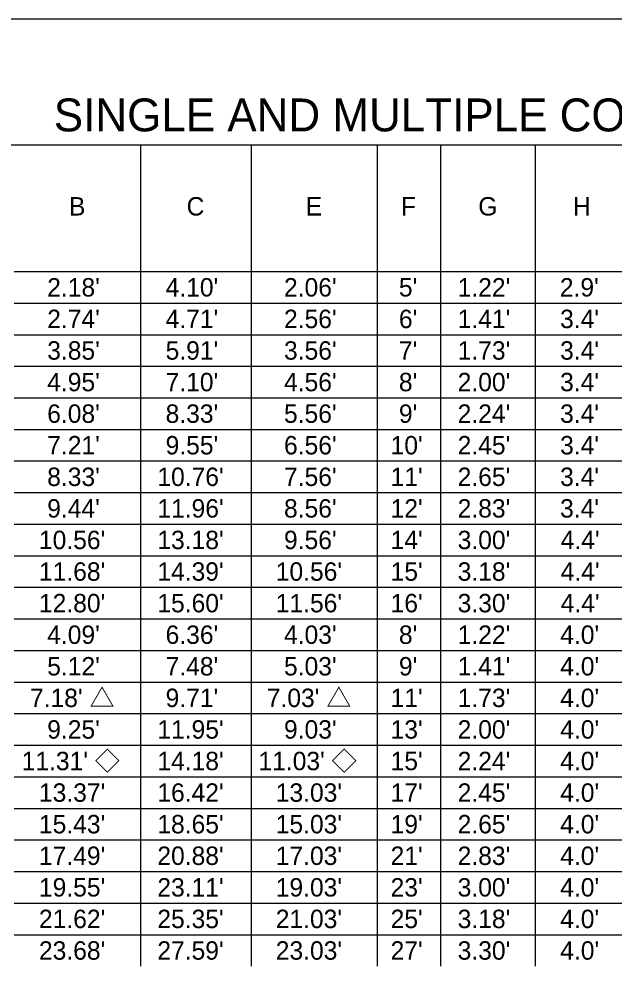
# Model space of a CAD drawing. Extents: x -1.3 to 14.6, y 0 to 8.4.
# Drawn here: x 4.058 to 6.32, y 4.842 to 8.43 of the extents above; entities that cross this region are included whole.
import ezdxf

# ---------------------------------------------------------------- set-up
doc = ezdxf.new("R2010")
doc.units = 0
doc.layers.add('Table', color=7, linetype='Continuous')

msp = doc.modelspace()

# ---------------------------------------------------------------- linework, layer by layer
at = {"layer": 'Table'}
msp.add_line((1.94, 8.43), (13.46, 8.43), dxfattribs=at)
for points in [[(13.46, 7.95), (11.78, 7.95), (10.1, 7.95), (8.42, 7.95), (8.06, 7.95), (6.38, 7.95), (6.02, 7.95), (5.66, 7.95), (5.42, 7.95), (4.94, 7.95), (4.52, 7.95), (4.04, 7.95), (3.62, 7.95), (3.2, 7.95), (2.9, 7.95), (2.6, 7.95), (2.3, 7.95), (1.94, 7.95)], [(4.52, 7.95), (4.52, 7.47), (4.52, 7.35), (4.52, 7.23), (4.52, 7.11), (4.52, 6.99), (4.52, 6.87), (4.52, 6.75), (4.52, 6.63), (4.52, 6.51), (4.52, 6.39), (4.52, 6.27), (4.52, 6.15), (4.52, 6.03), (4.52, 5.91), (4.52, 5.79), (4.52, 5.67), (4.52, 5.55), (4.52, 5.43), (4.52, 5.31), (4.52, 5.19), (4.52, 5.07), (4.52, 4.95), (4.52, 4.83)], [(4.94, 7.95), (4.94, 7.47), (4.94, 7.35), (4.94, 7.23), (4.94, 7.11), (4.94, 6.99), (4.94, 6.87), (4.94, 6.75), (4.94, 6.63), (4.94, 6.51), (4.94, 6.39), (4.94, 6.27), (4.94, 6.15), (4.94, 6.03), (4.94, 5.91), (4.94, 5.79), (4.94, 5.67), (4.94, 5.55), (4.94, 5.43), (4.94, 5.31), (4.94, 5.19), (4.94, 5.07), (4.94, 4.95), (4.94, 4.83)], [(5.42, 7.95), (5.42, 7.47), (5.42, 7.35), (5.42, 7.23), (5.42, 7.11), (5.42, 6.99), (5.42, 6.87), (5.42, 6.75), (5.42, 6.63), (5.42, 6.51), (5.42, 6.39), (5.42, 6.27), (5.42, 6.15), (5.42, 6.03), (5.42, 5.91), (5.42, 5.79), (5.42, 5.67), (5.42, 5.55), (5.42, 5.43), (5.42, 5.31), (5.42, 5.19), (5.42, 5.07), (5.42, 4.95), (5.42, 4.83)], [(5.66, 7.95), (5.66, 7.47), (5.66, 7.35), (5.66, 7.23), (5.66, 7.11), (5.66, 6.99), (5.66, 6.87), (5.66, 6.75), (5.66, 6.63), (5.66, 6.51), (5.66, 6.39), (5.66, 6.27), (5.66, 6.15), (5.66, 6.03), (5.66, 5.91), (5.66, 5.79), (5.66, 5.67), (5.66, 5.55), (5.66, 5.43), (5.66, 5.31), (5.66, 5.19), (5.66, 5.07), (5.66, 4.95), (5.66, 4.83)], [(6.02, 7.95), (6.02, 7.47), (6.02, 7.35), (6.02, 7.23), (6.02, 7.11), (6.02, 6.99), (6.02, 6.87), (6.02, 6.75), (6.02, 6.63), (6.02, 6.51), (6.02, 6.39), (6.02, 6.27), (6.02, 6.15), (6.02, 6.03), (6.02, 5.91), (6.02, 5.79), (6.02, 5.67), (6.02, 5.55), (6.02, 5.43), (6.02, 5.31), (6.02, 5.19), (6.02, 5.07), (6.02, 4.95), (6.02, 4.83)], [(4.04, 7.47), (4.52, 7.47), (4.94, 7.47), (5.42, 7.47), (5.66, 7.47), (6.02, 7.47), (6.38, 7.47), (6.8, 7.47), (7.22, 7.47), (7.64, 7.47), (8.06, 7.47), (8.42, 7.47), (8.84, 7.47), (9.26, 7.47), (9.68, 7.47), (10.1, 7.47), (10.52, 7.47), (10.94, 7.47), (11.36, 7.47), (11.78, 7.47), (12.2, 7.47), (12.62, 7.47), (13.04, 7.47), (13.46, 7.47)], [(4.04, 7.35), (4.52, 7.35), (4.94, 7.35), (5.42, 7.35), (5.66, 7.35), (6.02, 7.35), (6.38, 7.35), (6.8, 7.35), (7.22, 7.35), (7.64, 7.35), (8.06, 7.35), (8.42, 7.35), (8.84, 7.35), (9.26, 7.35), (9.68, 7.35), (10.1, 7.35), (10.52, 7.35), (10.94, 7.35), (11.36, 7.35), (11.78, 7.35), (12.2, 7.35), (12.62, 7.35), (13.04, 7.35), (13.46, 7.35)], [(4.04, 7.23), (4.52, 7.23), (4.94, 7.23), (5.42, 7.23), (5.66, 7.23), (6.02, 7.23), (6.38, 7.23), (6.8, 7.23), (7.22, 7.23), (7.64, 7.23), (8.06, 7.23), (8.42, 7.23), (8.84, 7.23), (9.26, 7.23), (9.68, 7.23), (10.1, 7.23), (10.52, 7.23), (10.94, 7.23), (11.36, 7.23), (11.78, 7.23), (12.2, 7.23), (12.62, 7.23), (13.04, 7.23), (13.46, 7.23)], [(4.04, 7.11), (4.52, 7.11), (4.94, 7.11), (5.42, 7.11), (5.66, 7.11), (6.02, 7.11), (6.38, 7.11), (6.8, 7.11), (7.22, 7.11), (7.64, 7.11), (8.06, 7.11), (8.42, 7.11), (8.84, 7.11), (9.26, 7.11), (9.68, 7.11), (10.1, 7.11), (10.52, 7.11), (10.94, 7.11), (11.36, 7.11), (11.78, 7.11), (12.2, 7.11), (12.62, 7.11), (13.04, 7.11), (13.46, 7.11)], [(4.04, 6.99), (4.52, 6.99), (4.94, 6.99), (5.42, 6.99), (5.66, 6.99), (6.02, 6.99), (6.38, 6.99), (6.8, 6.99), (7.22, 6.99), (7.64, 6.99), (8.06, 6.99), (8.42, 6.99), (8.84, 6.99), (9.26, 6.99), (9.68, 6.99), (10.1, 6.99), (10.52, 6.99), (10.94, 6.99), (11.36, 6.99), (11.78, 6.99), (12.2, 6.99), (12.62, 6.99), (13.04, 6.99), (13.46, 6.99)], [(4.04, 6.87), (4.52, 6.87), (4.94, 6.87), (5.42, 6.87), (5.66, 6.87), (6.02, 6.87), (6.38, 6.87), (6.8, 6.87), (7.22, 6.87), (7.64, 6.87), (8.06, 6.87), (8.42, 6.87), (8.84, 6.87), (9.26, 6.87), (9.68, 6.87), (10.1, 6.87), (10.52, 6.87), (10.94, 6.87), (11.36, 6.87), (11.78, 6.87), (12.2, 6.87), (12.62, 6.87), (13.04, 6.87), (13.46, 6.87)], [(4.04, 6.75), (4.52, 6.75), (4.94, 6.75), (5.42, 6.75), (5.66, 6.75), (6.02, 6.75), (6.38, 6.75), (6.8, 6.75), (7.22, 6.75), (7.64, 6.75), (8.06, 6.75), (8.42, 6.75), (8.84, 6.75), (9.26, 6.75), (9.68, 6.75), (10.1, 6.75), (10.52, 6.75), (10.94, 6.75), (11.36, 6.75), (11.78, 6.75), (12.2, 6.75), (12.62, 6.75), (13.04, 6.75), (13.46, 6.75)], [(4.04, 6.63), (4.52, 6.63), (4.94, 6.63), (5.42, 6.63), (5.66, 6.63), (6.02, 6.63), (6.38, 6.63), (6.8, 6.63), (7.22, 6.63), (7.64, 6.63), (8.06, 6.63), (8.42, 6.63), (8.84, 6.63), (9.26, 6.63), (9.68, 6.63), (10.1, 6.63), (10.52, 6.63), (10.94, 6.63), (11.36, 6.63), (11.78, 6.63), (12.2, 6.63), (12.62, 6.63), (13.04, 6.63), (13.46, 6.63)], [(4.04, 6.51), (4.52, 6.51), (4.94, 6.51), (5.42, 6.51), (5.66, 6.51), (6.02, 6.51), (6.38, 6.51), (6.8, 6.51), (7.22, 6.51), (7.64, 6.51), (8.06, 6.51), (8.42, 6.51), (8.84, 6.51), (9.26, 6.51), (9.68, 6.51), (10.1, 6.51), (10.52, 6.51), (10.94, 6.51), (11.36, 6.51), (11.78, 6.51), (12.2, 6.51), (12.62, 6.51), (13.04, 6.51), (13.46, 6.51)], [(4.04, 6.39), (4.52, 6.39), (4.94, 6.39), (5.42, 6.39), (5.66, 6.39), (6.02, 6.39), (6.38, 6.39), (6.8, 6.39), (7.22, 6.39), (7.64, 6.39), (8.06, 6.39), (8.42, 6.39), (8.84, 6.39), (9.26, 6.39), (9.68, 6.39), (10.1, 6.39), (10.52, 6.39), (10.94, 6.39), (11.36, 6.39), (11.78, 6.39), (12.2, 6.39), (12.62, 6.39), (13.04, 6.39), (13.46, 6.39)], [(4.04, 6.27), (4.52, 6.27), (4.94, 6.27), (5.42, 6.27), (5.66, 6.27), (6.02, 6.27), (6.38, 6.27), (6.8, 6.27), (7.22, 6.27), (7.64, 6.27), (8.06, 6.27), (8.42, 6.27), (8.84, 6.27), (9.26, 6.27), (9.68, 6.27), (10.1, 6.27), (10.52, 6.27), (10.94, 6.27), (11.36, 6.27), (11.78, 6.27), (12.2, 6.27), (12.62, 6.27), (13.04, 6.27), (13.46, 6.27)], [(4.04, 6.15), (4.52, 6.15), (4.94, 6.15), (5.42, 6.15), (5.66, 6.15), (6.02, 6.15), (6.38, 6.15), (6.8, 6.15), (7.22, 6.15), (7.64, 6.15), (8.06, 6.15), (8.42, 6.15), (8.84, 6.15), (9.26, 6.15), (9.68, 6.15), (10.1, 6.15), (10.52, 6.15), (10.94, 6.15), (11.36, 6.15), (11.78, 6.15), (12.2, 6.15), (12.62, 6.15), (13.04, 6.15), (13.46, 6.15)], [(4.04, 6.03), (4.52, 6.03), (4.94, 6.03), (5.42, 6.03), (5.66, 6.03), (6.02, 6.03), (6.38, 6.03), (6.8, 6.03), (7.22, 6.03), (7.64, 6.03), (8.06, 6.03), (8.42, 6.03), (8.84, 6.03), (9.26, 6.03), (9.68, 6.03), (10.1, 6.03), (10.52, 6.03), (10.94, 6.03), (11.36, 6.03), (11.78, 6.03), (12.2, 6.03), (12.62, 6.03), (13.04, 6.03), (13.46, 6.03)], [(4.04, 5.91), (4.52, 5.91), (4.94, 5.91), (5.42, 5.91), (5.66, 5.91), (6.02, 5.91), (6.38, 5.91), (6.8, 5.91), (7.22, 5.91), (7.64, 5.91), (8.06, 5.91), (8.42, 5.91), (8.84, 5.91), (9.26, 5.91), (9.68, 5.91), (10.1, 5.91), (10.52, 5.91), (10.94, 5.91), (11.36, 5.91), (11.78, 5.91), (12.2, 5.91), (12.62, 5.91), (13.04, 5.91), (13.46, 5.91)], [(4.04, 5.79), (4.52, 5.79), (4.94, 5.79), (5.42, 5.79), (5.66, 5.79), (6.02, 5.79), (6.38, 5.79), (6.8, 5.79), (7.22, 5.79), (7.64, 5.79), (8.06, 5.79), (8.42, 5.79), (8.84, 5.79), (9.26, 5.79), (9.68, 5.79), (10.1, 5.79), (10.52, 5.79), (10.94, 5.79), (11.36, 5.79), (11.78, 5.79), (12.2, 5.79), (12.62, 5.79), (13.04, 5.79), (13.46, 5.79)], [(4.04, 5.67), (4.52, 5.67), (4.94, 5.67), (5.42, 5.67), (5.66, 5.67), (6.02, 5.67), (6.38, 5.67), (6.8, 5.67), (7.22, 5.67), (7.64, 5.67), (8.06, 5.67), (8.42, 5.67), (8.84, 5.67), (9.26, 5.67), (9.68, 5.67), (10.1, 5.67), (10.52, 5.67), (10.94, 5.67), (11.36, 5.67), (11.78, 5.67), (12.2, 5.67), (12.62, 5.67), (13.04, 5.67), (13.46, 5.67)], [(4.04, 5.55), (4.52, 5.55), (4.94, 5.55), (5.42, 5.55), (5.66, 5.55), (6.02, 5.55), (6.38, 5.55), (6.8, 5.55), (7.22, 5.55), (7.64, 5.55), (8.06, 5.55), (8.42, 5.55), (8.84, 5.55), (9.26, 5.55), (9.68, 5.55), (10.1, 5.55), (10.52, 5.55), (10.94, 5.55), (11.36, 5.55), (11.78, 5.55), (12.2, 5.55), (12.62, 5.55), (13.04, 5.55), (13.46, 5.55)], [(4.04, 5.43), (4.52, 5.43), (4.94, 5.43), (5.42, 5.43), (5.66, 5.43), (6.02, 5.43), (6.38, 5.43), (6.8, 5.43), (7.22, 5.43), (7.64, 5.43), (8.06, 5.43), (8.42, 5.43), (8.84, 5.43), (9.26, 5.43), (9.68, 5.43), (10.1, 5.43), (10.52, 5.43), (10.94, 5.43), (11.36, 5.43), (11.78, 5.43), (12.2, 5.43), (12.62, 5.43), (13.04, 5.43), (13.46, 5.43)], [(4.04, 5.31), (4.52, 5.31), (4.94, 5.31), (5.42, 5.31), (5.66, 5.31), (6.02, 5.31), (6.38, 5.31), (6.8, 5.31), (7.22, 5.31), (7.64, 5.31), (8.06, 5.31), (8.42, 5.31), (8.84, 5.31), (9.26, 5.31), (9.68, 5.31), (10.1, 5.31), (10.52, 5.31), (10.94, 5.31), (11.36, 5.31), (11.78, 5.31), (12.2, 5.31), (12.62, 5.31), (13.04, 5.31), (13.46, 5.31)], [(4.04, 5.19), (4.52, 5.19), (4.94, 5.19), (5.42, 5.19), (5.66, 5.19), (6.02, 5.19), (6.38, 5.19), (6.8, 5.19), (7.22, 5.19), (7.64, 5.19), (8.06, 5.19), (8.42, 5.19), (8.84, 5.19), (9.26, 5.19), (9.68, 5.19), (10.1, 5.19), (10.52, 5.19), (10.94, 5.19), (11.36, 5.19), (11.78, 5.19), (12.2, 5.19), (12.62, 5.19), (13.04, 5.19), (13.46, 5.19)], [(4.04, 5.07), (4.52, 5.07), (4.94, 5.07), (5.42, 5.07), (5.66, 5.07), (6.02, 5.07), (6.38, 5.07), (6.8, 5.07), (7.22, 5.07), (7.64, 5.07), (8.06, 5.07), (8.42, 5.07), (8.84, 5.07), (9.26, 5.07), (9.68, 5.07), (10.1, 5.07), (10.52, 5.07), (10.94, 5.07), (11.36, 5.07), (11.78, 5.07), (12.2, 5.07), (12.62, 5.07), (13.04, 5.07), (13.46, 5.07)], [(4.04, 4.95), (4.52, 4.95), (4.94, 4.95), (5.42, 4.95), (5.66, 4.95), (6.02, 4.95), (6.38, 4.95), (6.8, 4.95), (7.22, 4.95), (7.64, 4.95), (8.06, 4.95), (8.42, 4.95), (8.84, 4.95), (9.26, 4.95), (9.68, 4.95), (10.1, 4.95), (10.52, 4.95), (10.94, 4.95), (11.36, 4.95), (11.78, 4.95), (12.2, 4.95), (12.62, 4.95), (13.04, 4.95), (13.46, 4.95)]]:
    msp.add_lwpolyline(points, dxfattribs=at)

# ---------------------------------------------------------------- texts
for s, height, p in [('SINGLE AND MULTIPLE CONCRETE PIPE DIMENSIONS AND QUANTITIES', 0.125, (4.1904, 8.0025)), ('B', 0.07, (4.2483, 7.6828)), ('C', 0.07, (4.6952, 7.6828)), ('E', 0.07, (5.1482, 7.6828)), ('F', 0.07, (5.5103, 7.6828)), ('G', 0.07, (5.8038, 7.6828)), ('H', 0.07, (6.1637, 7.6828))]:
    msp.add_text(s, height=height, dxfattribs=at).set_placement(p)
for s, p in [("2.18'", (4.1654, 7.375)), ("4.10'", (4.6154, 7.375)), ("2.06'", (5.0654, 7.375)), ("5'", (5.5021, 7.375)), ("1.22'", (5.7254, 7.375)), ("2.9'", (6.1138, 7.375)), ("2.74'", (4.1654, 7.255)), ("4.71'", (4.6154, 7.255)), ("2.56'", (5.0654, 7.255)), ("6'", (5.5021, 7.255)), ("1.41'", (5.7254, 7.255)), ("3.4'", (6.1147, 7.255)), ("3.85'", (4.1654, 7.135)), ("5.91'", (4.6154, 7.135)), ("3.56'", (5.0654, 7.135)), ("7'", (5.5021, 7.135)), ("1.73'", (5.7254, 7.135)), ("3.4'", (6.1147, 7.135)), ("4.95'", (4.1654, 7.015)), ("7.10'", (4.6154, 7.015)), ("4.56'", (5.0654, 7.015)), ("8'", (5.5021, 7.015)), ("2.00'", (5.7254, 7.015)), ("3.4'", (6.1147, 7.015)), ("6.08'", (4.1654, 6.895)), ("8.33'", (4.6154, 6.895)), ("5.56'", (5.0654, 6.895)), ("9'", (5.5021, 6.895)), ("2.24'", (5.7254, 6.895)), ("3.4'", (6.1147, 6.895)), ("7.21'", (4.1654, 6.775)), ("9.55'", (4.6154, 6.775)), ("6.56'", (5.0654, 6.775)), ("10'", (5.4706, 6.775)), ("2.45'", (5.7254, 6.775)), ("3.4'", (6.1147, 6.775)), ("8.33'", (4.1654, 6.655)), ("10.76'", (4.584, 6.655)), ("7.56'", (5.0654, 6.655)), ("11'", (5.4706, 6.655)), ("2.65'", (5.7254, 6.655)), ("3.4'", (6.1147, 6.655)), ("9.44'", (4.1654, 6.535)), ("11.96'", (4.584, 6.535)), ("8.56'", (5.0654, 6.535)), ("12'", (5.4706, 6.535)), ("2.83'", (5.7254, 6.535)), ("3.4'", (6.1147, 6.535)), ("10.56'", (4.134, 6.415)), ("13.18'", (4.584, 6.415)), ("9.56'", (5.0654, 6.415)), ("14'", (5.4706, 6.415)), ("3.00'", (5.7254, 6.415)), ("4.4'", (6.1169, 6.415)), ("11.68'", (4.134, 6.295)), ("14.39'", (4.584, 6.295)), ("10.56'", (5.034, 6.295)), ("15'", (5.4706, 6.295)), ("3.18'", (5.7254, 6.295)), ("4.4'", (6.1169, 6.295)), ("12.80'", (4.134, 6.175)), ("15.60'", (4.584, 6.175)), ("11.56'", (5.034, 6.175)), ("16'", (5.4706, 6.175)), ("3.30'", (5.7254, 6.175)), ("4.4'", (6.1169, 6.175)), ("4.09'", (4.1654, 6.055)), ("6.36'", (4.6154, 6.055)), ("4.03'", (5.0654, 6.055)), ("8'", (5.5021, 6.055)), ("1.22'", (5.7254, 6.055)), ("4.0'", (6.1153, 6.055)), ("5.12'", (4.1654, 5.935)), ("7.48'", (4.6154, 5.935)), ("5.03'", (5.0654, 5.935)), ("9'", (5.5021, 5.935)), ("1.41'", (5.7254, 5.935)), ("4.0'", (6.1153, 5.935)), ("7.18' △", (4.1, 5.815)), ("9.71'", (4.6154, 5.815)), ("7.03' △", (5, 5.815)), ("11'", (5.4706, 5.815)), ("1.73'", (5.7254, 5.815)), ("4.0'", (6.1153, 5.815)), ("9.25'", (4.1654, 5.695)), ("11.95'", (4.584, 5.695)), ("9.03'", (5.0654, 5.695)), ("13'", (5.4706, 5.695)), ("2.00'", (5.7254, 5.695)), ("4.0'", (6.1153, 5.695)), ("11.31' ◇", (4.0683, 5.575)), ("14.18'", (4.584, 5.575)), ("11.03' ◇", (4.9683, 5.575)), ("15'", (5.4706, 5.575)), ("2.24'", (5.7254, 5.575)), ("4.0'", (6.1153, 5.575)), ("13.37'", (4.134, 5.455)), ("16.42'", (4.584, 5.455)), ("13.03'", (5.034, 5.455)), ("2.45'", (5.7254, 5.455)), ("4.0'", (6.1153, 5.455)), ("17'", (5.4706, 5.455)), ("15.43'", (4.134, 5.335)), ("18.65'", (4.584, 5.335)), ("15.03'", (5.034, 5.335)), ("19'", (5.4706, 5.335)), ("2.65'", (5.7254, 5.335)), ("4.0'", (6.1153, 5.335)), ("17.49'", (4.134, 5.215)), ("20.88'", (4.584, 5.215)), ("17.03'", (5.034, 5.215)), ("21'", (5.4706, 5.215)), ("2.83'", (5.7254, 5.215)), ("4.0'", (6.1153, 5.215)), ("19.55'", (4.134, 5.095)), ("23.11'", (4.584, 5.095)), ("19.03'", (5.034, 5.095)), ("23'", (5.4706, 5.095)), ("3.00'", (5.7254, 5.095)), ("4.0'", (6.1153, 5.095)), ("21.62'", (4.134, 4.975)), ("25.35'", (4.584, 4.975)), ("21.03'", (5.034, 4.975)), ("25'", (5.4706, 4.975)), ("3.18'", (5.7254, 4.975)), ("4.0'", (6.1153, 4.975)), ("23.68'", (4.134, 4.855)), ("27.59'", (4.584, 4.855)), ("23.03'", (5.034, 4.855)), ("27'", (5.4706, 4.855)), ("3.30'", (5.7254, 4.855)), ("4.0'", (6.1153, 4.855))]:
    msp.add_text(s, height=0.07, rotation=0, dxfattribs=at).set_placement(p)

doc.saveas('drawing.dxf')
